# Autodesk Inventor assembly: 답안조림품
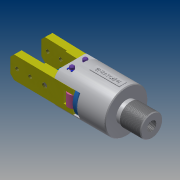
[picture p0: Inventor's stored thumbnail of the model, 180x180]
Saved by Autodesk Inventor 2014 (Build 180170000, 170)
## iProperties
Created: 2019-02
Part Number: 답안조림품
Document SubType Name: Assembly
Designer: 603-18
Author: 603-18
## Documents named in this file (11)
- C:\Users\603-18\Desktop\490208V1002\답안조림품.iam
- C:\Users\603-18\Desktop\490208V1002\본체.ipt
- C:\Users\603-18\Desktop\490208V1002\E-링.ipt
- C:\Users\603-18\Desktop\490208V1002\O-링.ipt
- C:\Users\603-18\Desktop\490208V1002\가이드핀.ipt
- C:\Users\603-18\Desktop\490208V1002\부시.ipt
- C:\Users\603-18\Desktop\490208V1002\스프링.ipt
- C:\Users\603-18\Desktop\490208V1002\평행핀 6x28.ipt
- C:\Users\603-18\Desktop\490208V1002\피스톤.ipt
- C:\Users\603-18\Desktop\490208V1002\핀.ipt
- C:\Users\603-18\Desktop\490208V1002\핑거.ipt
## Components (13 placed, 6 different names)
1. E-링:1 — 각도:2
2. O-링:1
3. 가이드핀:1
4. 피스톤:1 — 각도:5
5. 핀:1
6. 핑거:1 — 각도:3
7. 핑거:2 — 각도:4
8. 가이드핀:2
9. 핀:2 — 각도:1, 각도:2
10. E-링:2 — 각도:1
11. E-링:3
12. E-링:5
13. O-링:2
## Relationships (5: Angle 5)
- 각도:1 [Angle]: 핀:2 ↔ E-링:2
- 각도:2 [Angle]: E-링:1 ↔ 핀:2
- 각도:3 [Angle]: 핑거:1
- 각도:4 [Angle]: 핑거:2
- 각도:5 [Angle]: 피스톤:1
